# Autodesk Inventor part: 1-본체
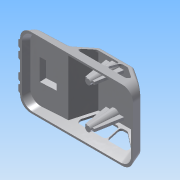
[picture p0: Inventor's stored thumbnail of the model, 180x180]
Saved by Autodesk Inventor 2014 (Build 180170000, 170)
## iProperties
Created: 2015-05
Part Number: 1-본체
Material: ABS 플라스틱
Document SubType Name: Modeling
Designer: Administrator
Density: 1.06 g/cm^3
Appearance: 매끄러움 - 흰색
Mass: 32.2965 g
Surface Area: 294.052 cm^2
Volume: 30.4684 cm^3
Author: Administrator
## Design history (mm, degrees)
sketch "스케치1"
  geometry: L1 (0, 0)-(122, 0); L2 (54.451, 31)-(92, 31); L3 (92, 31)-(119.053, 11); L4 (119.053, 11)-(122, 0); L5 (0, 0)-(2.412, 9); L6 (2.412, 9)-(42, 11.075); L7 (42, 11.075)-(54.451, 31)
  constraints: 14 end point, 1 horizontal, 1 parallel
  dimensions: "d0" = 122 distance of L1.start L1.end; "d7" = 105 deg angle of L1 L4; "d8" = 31 distance between parallel lines of L1 L2; "d9" = 30 horizontal distance of L1.end L2.end; "d13" = 20 vertical distance of L3.end L2.end; "d16" = 105 deg angle of L5 L1; "d17" = 42 horizontal distance of L6.end L1.start; "d18" = 125 deg angle of L7 L6; "d19" = 9 distance from line of L5.end L1; "d22" = 3 deg angle of L1 L6
extrude "돌출1" new body sketch "스케치1" distance "d23" = 76; taper "d24" = 0 deg
sketch "스케치7"
  geometry: L1 (0, 0)-(0, 76) reference; L2 (31, 0)-(31, 76) reference; L3 (0, 76)-(31, 67.694); L4 (0, 0)-(31, 8.306); L5 (0, 76)-(11, 76) reference; L6 (11, 76)-(31, 76) reference; L7 (0, 0)-(11, 0) reference; L8 (11, 0)-(31, 0) reference
  constraints: 4 end point, 2 point on line
  dimensions: "d53" = 105 deg angle of L1 L4; "d54" = 105 deg angle of L3 L1
extrude "돌출5" cut sketch "스케치7" stored distance "d55" = 0; taper "d56" = 0 deg
sketch "스케치2"
  geometry: L1 (39.643, 76)-(0, 76) reference; L2 (0, 76)-(0, 0) reference; L3 (9.821, 51)-(29.821, 51); L4 (29.821, 51)-(29.821, 25); L5 (29.821, 25)-(9.821, 25); L6 (9.821, 25)-(9.821, 51); L7 (9.821, 51)-(29.821, 25); L8 (29.821, 51)-(9.821, 25); 6 further points
  constraints: 12 end point, 6 midpoint, 2 parallel, 1 horizontal, 1 horizontal alignment, 1 perpendicular, 1 vertical alignment
  dimensions: "d26" = 20 distance of L3.start L3.end; "d27" = 26 distance of L3.end L4.end
extrude "돌출2" join sketch "스케치2" distance "d28" = 5; taper "d29" = -20 deg
feature "쉘1" dims "d30" = 2
sketch "스케치3"
  geometry: L1 (119.053, 11)-(92, 31) reference; L2 (92, 31)-(54.451, 31) reference; L3 (54.451, 31)-(42, 11.075) reference; L4 (81.849, 26)-(57.222, 26); L5 (82.642, 26)-(82.642, 11); L6 (82.642, 11)-(110.642, 11); L7 (110.642, 11)-(90.352, 26); L8 (90.352, 26)-(82.642, 26); L9 (47.849, 11)-(57.222, 26); L10 (81.849, 26)-(81.849, 11); L11 (81.849, 11)-(47.849, 11)
  constraints: 16 end point, 4 perpendicular, 2 parallel
  dimensions: "d31" = 5 distance between parallel lines of L3 L9; "d32" = 5 distance between parallel lines of L4 L2; "d34" = 34 distance of L10.end L9.start; "d35" = 15 distance from line of L11 L4.end; "d36" = 5 distance between parallel lines of L2 L8; "d37" = 5 distance between parallel lines of L1 L7; "d38" = 28 distance of L5.end L6.end; "d39" = 15 distance between parallel lines of L6 L8
extrude "돌출3" cut sketch "스케치3" stored distance "d40" = 0; taper "d41" = 0 deg
node "작업 평면3"
sketch "스케치9"
  geometry: A1 r 4 centre (0, 59) between (0, 55) and (0, 63); A2 r 4 centre (0, 48) between (0, 44) and (0, 52); A3 r 4 centre (0, 28) between (0, 24) and (0, 32); A4 r 4 centre (0, 17) between (0, 13) and (0, 21); 3 further points
  constraints: 8 point on circle, 4 centre point, 3 equal radius, 14 other
  dimensions: "d58" = 8 diameter of A1; "d59" = 11 distance of A2.centre A1.centre; "d60" = 10 distance of A2.centre point (0, 38); "d61" = 11 distance of A4.centre A3.centre; "d62" = 10 distance of A3.centre point (0, 38)
extrude "돌출6" join sketch "스케치9" stored distance "d63" = 5; taper "d64" = 0 deg
sketch "스케치16"
  geometry: L1 (-54.451, 8.306)-(-54.451, 67.694) reference; L2 (-54.451, 67.694)-(-92, 67.694) reference; L3 (-92, 8.306)-(-92, 67.694) reference; L4 (-92, 8.306)-(-54.451, 8.306) reference; C1 r 3 at (-73.225, 60); C2 r 3 at (-73.225, 16); 4 further points
  constraints: 3 vertical alignment, 2 centre point, 2 midpoint, 1 horizontal alignment
  dimensions: "d85" = 6 diameter of C2; "d86" = 6 diameter of C1; "d87" = 22 distance of point (-73.225, 38) C2.centre; "d88" = 22 distance of C1.centre point (-73.225, 38)
extrude "돌출10" join sketch "스케치16" stored distance "d89" = 5; taper "d90" = 4 deg
node "작업 평면6"
sketch "스케치19"
  geometry: L1 (55.559, 29)-(91.341, 29) reference; L2 (63.689, 29)-(68.45, 2); L3 (68.45, 2)-(78.45, 2); L4 (78.45, 2)-(83.211, 29); L5 (0, 0)-(122, 0) reference; 2 further points
  constraints: 6 end point, 2 midpoint, 2 point on line, 1 equal length, 1 parallel, 1 vertical alignment
  dimensions: "d96" = 20 deg angle of L4 L2; "d97" = 10 distance of L2.end L3.end; "d98" = 2 distance between parallel lines of L5 L3
extrude "돌출12" join sketch "스케치19" stored distance "d99" = 3; taper "d100" = 0 deg
fillet "모깎기1" dims "d101" = 3
node "작업 평면7"
sketch "스케치20"
  geometry: L1 (55.559, 29)-(91.341, 29) reference; L2 (0, 0)-(122, 0) reference; L3 (63.689, 29)-(68.45, 2); L4 (68.45, 2)-(78.45, 2); L5 (78.45, 2)-(83.211, 29); 2 further points
  constraints: 6 end point, 2 midpoint, 2 point on line, 1 equal length, 1 parallel, 1 vertical alignment
  dimensions: "d103" = 2 distance between parallel lines of L2 L4; "d104" = 20 deg angle of L5 L3; "d105" = 10 distance of L3.end L4.end
extrude "돌출13" join sketch "스케치20" stored distance "d106" = 3; taper "d107" = 0 deg
fillet "모깎기2" dims "d108" = 3
fillet "모깎기3" dims "d109" = 3
fillet "모깎기5" dims "d111" = 12
fillet "모깎기6" dims "d112" = 3
fillet "모깎기7" dims "d113" = 3
chamfer "모따기1" distance "d114" = 1; stored, may be unused: second distance "d115" = 2, angle "d116" = 45 deg
node "솔리드1"
other parameters: "d57" = -2, "d95" = 16
